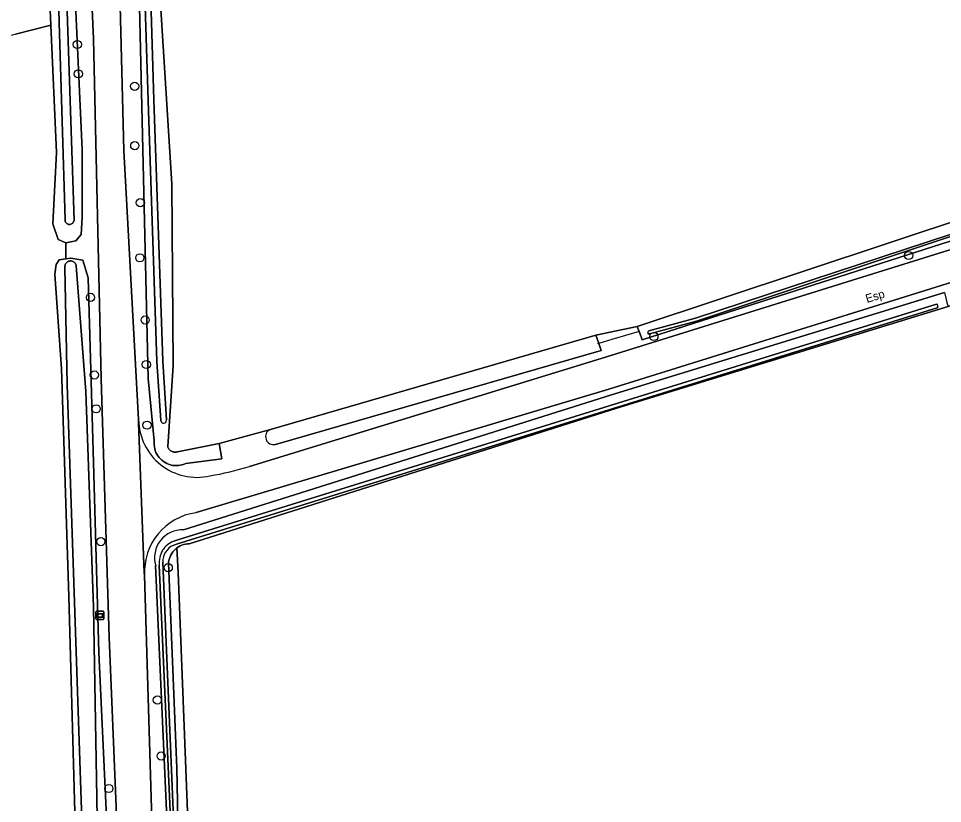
# Model space of a CAD drawing. Extents: x 161385 to 162589, y 388479 to 389756.
# Drawn here: x 161804.9 to 161915.1, y 389332.8 to 389426.5 of the extents above; entities that cross this region are included whole.
import ezdxf

# ---------------------------------------------------------------- set-up
doc = ezdxf.new("R2010")
doc.units = 0
for name, color, linetype in [('IMGEO_Boom', 7, 'Continuous'), ('IMGEO_Bouwland', 7, 'Continuous'), ('IMGEO_Duiker', 7, 'Continuous'), ('IMGEO_Groenvoorziening', 7, 'Continuous'), ('IMGEO_Loofbos', 7, 'Continuous'), ('IMGEO_Oever', 7, 'Continuous'), ('IMGEO_Openbare_ruimte_label', 7, 'Continuous'), ('IMGEO_Rijbaan_lokaal_gesloten', 7, 'Continuous'), ('IMGEO_Verklikker', 7, 'Continuous'), ('IMGEO_Waterloop', 7, 'Continuous')]:
    doc.layers.add(name, color=color, linetype=linetype)

msp = doc.modelspace()

# ---------------------------------------------------------------- linework, layer by layer
at = {"layer": 'IMGEO_Boom'}
for centre in [(161811.95, 389423.37), (161812.07, 389419.87), (161818.79, 389418.39), (161818.81, 389411.3), (161819.47, 389404.5), (161819.41, 389397.92), (161911.08, 389398.2), (161813.53, 389393.2), (161820.05, 389390.51), (161880.71, 389388.54), (161820.19, 389385.2), (161814, 389383.96), (161814.21, 389379.91), (161820.28, 389377.96), (161814.76, 389364.08), (161822.8, 389360.97), (161821.51, 389345.19), (161821.96, 389338.51), (161815.72, 389334.63)]:
    msp.add_circle(centre, 0.489, dxfattribs=at)
at = {"layer": 'IMGEO_Bouwland'}
for points in [[(161820.45, 389451.02), (161823.24, 389406.73), (161823.39, 389385.03), (161822.74, 389375.42), (161822.76, 389375.35), (161822.8, 389375.27), (161822.83, 389375.2), (161822.88, 389375.13), (161822.93, 389375.06), (161822.99, 389375), (161823.05, 389374.95), (161823.12, 389374.9), (161823.19, 389374.86), (161823.26, 389374.82), (161823.34, 389374.79), (161823.42, 389374.77), (161823.5, 389374.76), (161823.58, 389374.75), (161823.67, 389374.75), (161823.75, 389374.76), (161823.83, 389374.77), (161823.91, 389374.79), (161828.86, 389375.76), (161834.99, 389377.46), (161873.79, 389388.71), (161878.71, 389389.73), (161989.22, 389426.42)], [(161924.24, 389389.68), (161923.3, 389394.84), (161915.78, 389392.1), (161876.28, 389380.01), (161825.31, 389363.82), (161825.09, 389363.81), (161824.86, 389363.77), (161824.64, 389363.72), (161824.43, 389363.65), (161824.22, 389363.56), (161824.03, 389363.45), (161823.84, 389363.32), (161824, 389360.41), (161827.33, 389274.85), (161859.89, 389276.6), (161886.85, 389279.08), (161944.1, 389287.48)]]:
    msp.add_lwpolyline(points, dxfattribs=at)
at = {"layer": 'IMGEO_Duiker'}
msp.add_lwpolyline([(161878.94, 389389.15), (161875.71, 389388.18), (161874.14, 389387.71), (161874, 389387.67)], dxfattribs=at)
at = {"layer": 'IMGEO_Groenvoorziening'}
for points in [[(161803.61, 389506.63), (161806.15, 389500), (161807.11, 389497.5), (161809.67, 389488.19), (161813.64, 389468.06), (161815.8, 389449.75), (161816.99, 389431.15), (161817.52, 389410.72), (161819.27, 389378.64)], [(161822.47, 389183.9), (161819.9, 389250), (161818.24, 389292.85), (161817.88, 389301.55), (161815.76, 389352.66), (161814.81, 389383.51), (161813.89, 389424.04), (161813.4, 389434.81), (161812.54, 389448.61), (161810.15, 389467.29), (161806.16, 389487.18), (161804.33, 389495.22)], [(162015.57, 389425.19), (162052.22, 389436.6), (162077.56, 389444.49), (162110.6, 389453.36), (162116.48, 389455.97), (162132.77, 389460.73), (162149.28, 389466.12), (162149.51, 389465.17), (162151.86, 389465.92), (162152.81, 389469.35), (162149.94, 389468.39), (162101.79, 389453.37), (162051.71, 389438.12), (162010.92, 389425.7), (162000, 389422.15), (161923.01, 389397.14), (161875.33, 389382.27), (161826.12, 389367.53)], [(161834.99, 389377.46), (161828.86, 389375.76), (161829.18, 389373.96), (161824.91, 389373.4), (161824.69, 389373.31), (161824.47, 389373.23), (161824.24, 389373.18), (161824.01, 389373.15), (161823.77, 389373.14), (161823.54, 389373.15), (161823.3, 389373.17), (161823.07, 389373.23), (161822.85, 389373.3), (161822.63, 389373.39), (161822.42, 389373.5), (161822.22, 389373.63), (161822.04, 389373.77), (161821.87, 389373.93), (161821.71, 389374.11), (161821.57, 389374.3), (161821.45, 389374.5), (161821.34, 389374.71), (161821.26, 389374.93), (161821.19, 389375.16), (161821.15, 389375.39), (161821.13, 389375.62), (161821.12, 389375.86), (161821.14, 389376.09), (161820.42, 389383.54), (161819.1, 389439.9)], [(161811.61, 389430.85), (161812.54, 389410.84), (161812.53, 389402.73), (161812.43, 389400.71), (161811.8, 389399.94), (161810.6, 389399.73), (161810.58, 389397.81), (161811.2, 389397.88), (161812.6, 389397.63), (161813.27, 389395.52), (161813.9, 389373.52), (161814.54, 389350.83), (161815.58, 389327.78), (161816.24, 389306.78), (161816.21, 389297.23), (161817.06, 389274.16), (161818.28, 389246.31), (161819.3, 389221.36)], [(161993.88, 389428.52), (161989.22, 389426.42), (161989.4, 389425.6), (161989.65, 389424.43), (161918.01, 389400.54), (161879.32, 389388.15), (161879.02, 389388.93), (161878.94, 389389.15), (161878.71, 389389.73), (161873.79, 389388.71), (161874.11, 389387.82), (161874.14, 389387.71), (161874.44, 389386.89), (161835.6, 389375.67)], [(161832.48, 389373.05), (161874.41, 389385.9), (161919.07, 389399.82), (162000, 389426.14)], [(161824.61, 389365.48), (161875.64, 389381.59), (161915.36, 389393.78), (161915.57, 389392.95), (161915.65, 389392.6), (161915.78, 389392.1), (161923.3, 389394.84), (161923.24, 389395.11), (161923.11, 389395.64), (161922.91, 389396.45), (161969.32, 389410.88), (161970.06, 389411.11), (162000, 389420.42), (162010.32, 389423.62), (162010.66, 389422.78), (162011.08, 389421.76), (162000, 389418.36), (161974.9, 389410.66), (161975.16, 389409.79), (161974.45, 389409.6), (161974.71, 389408.55), (161987.23, 389412.43), (162020.79, 389422.67)], [(161823.95, 389301.85), (161821.3, 389361.22)], [(161819.99, 389360.06), (161821.73, 389301.74), (161823.28, 389250), (161825.77, 389184.1)]]:
    msp.add_lwpolyline(points, dxfattribs=at)
msp.add_lwpolyline([(161824, 389360.41), (161823.84, 389363.32), (161823.66, 389363.18), (161823.5, 389363.02), (161823.36, 389362.85), (161823.23, 389362.66), (161823.11, 389362.47), (161823.02, 389362.26), (161822.94, 389362.05), (161822.88, 389361.83), (161822.84, 389361.61), (161822.83, 389361.54), (161823.81, 389337.04), (161824.18, 389318.85), (161825.98, 389274.78), (161827.33, 389274.85)], close=True, dxfattribs=at)
for centre, radius, start, end in [((161826.23, 389378.7), 6.96, 180.5146, 282.7849), ((161835.36, 389376.59), 0.95, 113.342, 284.6185), ((161821.17, 389409.71), 38.37, 279.9026, 287.1432), ((161827.07, 389360.49), 7.1, 97.711, 183.4599), ((161824.48, 389362.17), 3.31, 87.6408, 196.6651)]:
    msp.add_arc(centre, radius, start, end, dxfattribs=at)
at = {"layer": 'IMGEO_Loofbos'}
msp.add_lwpolyline([(161808.81, 389425.67), (161808.7, 389428.38), (161808.59, 389430.65), (161808.68, 389431.62), (161809.55, 389432.13), (161810.03, 389432.1), (161809.88, 389436.24), (161808.82, 389435.47), (161807.74, 389435.14), (161807.42, 389436.2), (161802.27, 389434.35), (161794.13, 389432.6), (161776.69, 389428.35), (161757.68, 389423.46), (161743.62, 389419.4), (161742.64, 389408.7), (161760.31, 389413.8), (161779.12, 389418.64), (161796.38, 389422.84), (161804.59, 389424.61)], close=True, dxfattribs=at)
msp.add_lwpolyline([(161731.43, 389292.15), (161809.61, 389302.69), (161812.61, 389303.11), (161812.24, 389309.63), (161811.62, 389333.26), (161810.96, 389357.54), (161810.08, 389384.67), (161809.29, 389395.96), (161809.45, 389397.13), (161809.81, 389397.68), (161810.58, 389397.81), (161810.6, 389399.73), (161809.68, 389400.12), (161809.05, 389401.99), (161809.48, 389410.49), (161808.81, 389425.67), (161804.59, 389424.61)], dxfattribs=at)
at = {"layer": 'IMGEO_Oever'}
for points in [[(161821.96, 389378.42), (161821.91, 389378.53), (161821.46, 389385.56), (161820.41, 389416.69), (161819.7, 389439.19), (161818.14, 389460.28), (161816.84, 389468.86), (161812.8, 389487.76), (161811.27, 389494.42), (161808.33, 389503.15)], [(161808.86, 389503.38), (161811.95, 389494.51), (161813.47, 389487.84), (161817.52, 389468.95), (161818.82, 389460.36), (161820.39, 389439.29), (161821.08, 389416.78)], [(161819.1, 389439.9), (161820.42, 389383.54), (161821.14, 389376.09), (161821.12, 389375.86), (161821.13, 389375.62), (161821.15, 389375.39), (161821.19, 389375.16), (161821.26, 389374.93), (161821.34, 389374.71), (161821.45, 389374.5), (161821.57, 389374.3), (161821.71, 389374.11), (161821.87, 389373.93), (161822.04, 389373.77), (161822.22, 389373.63), (161822.42, 389373.5), (161822.63, 389373.39), (161822.85, 389373.3), (161823.07, 389373.23), (161823.3, 389373.17), (161823.54, 389373.15), (161823.77, 389373.14), (161824.01, 389373.15), (161824.24, 389373.18), (161824.47, 389373.23), (161824.69, 389373.31), (161824.91, 389373.4), (161829.18, 389373.96), (161828.86, 389375.76), (161823.91, 389374.79), (161823.83, 389374.77), (161823.75, 389374.76), (161823.67, 389374.75), (161823.58, 389374.75), (161823.5, 389374.76), (161823.42, 389374.77), (161823.34, 389374.79), (161823.26, 389374.82), (161823.19, 389374.86), (161823.12, 389374.9), (161823.05, 389374.95), (161822.99, 389375), (161822.93, 389375.06), (161822.88, 389375.13), (161822.83, 389375.2), (161822.8, 389375.27), (161822.76, 389375.35), (161822.74, 389375.42), (161823.39, 389385.03), (161823.24, 389406.73), (161820.45, 389451.02)], [(161810.64, 389430.92), (161811.59, 389402.4), (161811.44, 389402.06), (161811.1, 389401.89), (161811.05, 389401.89), (161811, 389401.89), (161810.96, 389401.89), (161810.91, 389401.9), (161810.86, 389401.92), (161810.82, 389401.94), (161810.77, 389401.96), (161810.73, 389401.99), (161810.7, 389402.02), (161810.66, 389402.05), (161810.63, 389402.09), (161810.6, 389402.12), (161810.57, 389402.17), (161810.55, 389402.21), (161810.53, 389402.26), (161810.52, 389402.3), (161810.51, 389402.35), (161810.51, 389402.4), (161810.51, 389402.45), (161809.8, 389425.98), (161809.66, 389430.77)], [(161988.29, 389424.39), (161988.29, 389424.35), (161988.22, 389424.27), (161988.2, 389424.25), (161988.09, 389424.21), (161970.95, 389418.43), (161944.43, 389409.78), (161916.2, 389400.52), (161885.78, 389390.38), (161880.2, 389388.85), (161880.04, 389388.86), (161880.01, 389388.88), (161880, 389388.9)], [(161879.99, 389389.11), (161880.11, 389389.21), (161885.68, 389390.74), (161916.14, 389400.74), (161930.23, 389405.46), (161944.37, 389410), (161970.89, 389418.71)], [(161821.08, 389416.78), (161822.14, 389385.64), (161822.58, 389378.61)], [(161819.3, 389221.36), (161818.28, 389246.31), (161817.06, 389274.16), (161816.21, 389297.23), (161816.24, 389306.78), (161815.58, 389327.78), (161814.54, 389350.83), (161813.9, 389373.52), (161813.27, 389395.52), (161812.6, 389397.63), (161811.2, 389397.88), (161810.58, 389397.81), (161809.81, 389397.68), (161809.45, 389397.13), (161809.29, 389395.96), (161810.08, 389384.67), (161810.96, 389357.54), (161811.62, 389333.26), (161812.24, 389309.63), (161812.61, 389303.11), (161813.67, 389283.96), (161814.96, 389258.6), (161815.63, 389234.8)], [(161813.36, 389304.94), (161810.76, 389382.77), (161810.48, 389396.81), (161810.48, 389396.84), (161810.48, 389396.9), (161810.49, 389396.96), (161810.5, 389397.02), (161810.51, 389397.08), (161810.53, 389397.14), (161810.56, 389397.19), (161810.59, 389397.24), (161810.62, 389397.29), (161810.66, 389397.34), (161810.71, 389397.38), (161810.75, 389397.42), (161810.8, 389397.45), (161810.86, 389397.48), (161810.91, 389397.51), (161810.97, 389397.53), (161811.03, 389397.54), (161811.09, 389397.55), (161811.12, 389397.55), (161811.18, 389397.55), (161811.24, 389397.55), (161811.3, 389397.54), (161811.36, 389397.52), (161811.41, 389397.5), (161811.47, 389397.48), (161811.52, 389397.45), (161811.57, 389397.41), (161811.62, 389397.37), (161811.66, 389397.33), (161811.7, 389397.28), (161811.73, 389397.23), (161811.76, 389397.18), (161811.79, 389397.12), (161811.81, 389397.07), (161811.82, 389397.01), (161811.83, 389396.95), (161812.98, 389381.98), (161813.88, 389356.25), (161814.79, 389303.88)], [(161915.36, 389393.78), (161875.64, 389381.59), (161824.61, 389365.48)], [(161823.48, 389364.12), (161824.05, 389364.32), (161914.39, 389392.4), (161914.51, 389392.35)], [(161823.81, 389337.04), (161822.83, 389361.54), (161822.84, 389361.61), (161822.88, 389361.83), (161822.94, 389362.05), (161823.02, 389362.26), (161823.11, 389362.47), (161823.23, 389362.66), (161823.36, 389362.85), (161823.5, 389363.02), (161823.66, 389363.18), (161823.84, 389363.32), (161824.03, 389363.45), (161824.22, 389363.56), (161824.43, 389363.65), (161824.64, 389363.72), (161824.86, 389363.77), (161825.09, 389363.81), (161825.31, 389363.82), (161876.28, 389380.01), (161915.78, 389392.1)], [(161914.58, 389392.07), (161914.48, 389391.97), (161823.79, 389363.78)], [(161823.79, 389363.78), (161823.4, 389363.63)], [(161822.16, 389361.63), (161823.99, 389317.71), (161825.71, 389274.91), (161825.67, 389274.77), (161825.63, 389274.73), (161825.56, 389274.72), (161825.49, 389274.74), (161825.46, 389274.77), (161825.4, 389274.91), (161823.85, 389313.22), (161821.71, 389361.27)], [(161821.3, 389361.22), (161823.95, 389301.85), (161825.17, 389274.39), (161825.33, 389273.84), (161825.52, 389273.7), (161825.69, 389273.77), (161825.73, 389273.79), (161825.99, 389274.56), (161825.98, 389274.78), (161824.18, 389318.85), (161823.81, 389337.04)]]:
    msp.add_lwpolyline(points, dxfattribs=at)
for points in [[(161811.61, 389430.85), (161811.04, 389432.11), (161810.03, 389432.1), (161809.55, 389432.13), (161808.68, 389431.62), (161808.59, 389430.65), (161808.7, 389428.38), (161808.81, 389425.67), (161809.48, 389410.49), (161809.05, 389401.99), (161809.68, 389400.12), (161810.6, 389399.73), (161811.8, 389399.94), (161812.43, 389400.71), (161812.53, 389402.73), (161812.54, 389410.84)], [(161989.65, 389424.43), (161989.4, 389425.6), (161989.22, 389426.42), (161878.71, 389389.73), (161878.94, 389389.15), (161879.02, 389388.93), (161879.32, 389388.15), (161918.01, 389400.54)]]:
    msp.add_lwpolyline(points, close=True, dxfattribs=at)
for centre, radius, start, end in [((161914.36, 389392.16), 0.234, 336.7846, 51.386), ((161880.3, 389389.01), 0.325, 161.7242, 200.4075), ((161822.29, 389378.56), 0.366, 203.164, 267.6681), ((161822.27, 389378.51), 0.314, 270.6274, 319.7514), ((161822.03, 389378.58), 0.551, 330.9939, 3.6273), ((161824.48, 389362.17), 3.31, 87.6408, 196.6651), ((161824.48, 389361.45), 2.85, 110.6205, 146.8708), ((161825.37, 389361.37), 3.66, 153.4094, 181.491), ((161824.26, 389361.71), 2.1, 114.1249, 182.1801)]:
    msp.add_arc(centre, radius, start, end, dxfattribs=at)
at = {"layer": 'IMGEO_Rijbaan_lokaal_gesloten'}
for points in [[(162274.51, 389513.54), (162284.77, 389517.62), (162283.07, 389521.76), (162282.4, 389521.48), (162273.98, 389518.09), (162256.73, 389511.13), (162234.04, 389502.53), (162227.24, 389500), (162209.08, 389493.03), (162180.59, 389482.67), (162149.26, 389472.47), (162113.07, 389461.06), (162103.55, 389458.09), (162050.46, 389441.86), (162014.71, 389430.93), (162014.07, 389430.72), (162008.66, 389428.95), (162007.84, 389428.69), (162000, 389426.14), (161919.07, 389399.82), (161874.41, 389385.9), (161832.48, 389373.05)], [(161826.12, 389367.53), (161875.33, 389382.27), (161923.01, 389397.14), (162000, 389422.15), (162010.92, 389425.7), (162051.71, 389438.12), (162101.79, 389453.37), (162149.94, 389468.39), (162152.81, 389469.35), (162156.6, 389470.63), (162181.39, 389478.96), (162191.34, 389482.09), (162232.31, 389497.1), (162253.52, 389505.21), (162274.51, 389513.54)], [(161825.77, 389184.1), (161823.28, 389250), (161821.73, 389301.74), (161819.99, 389360.06), (161819.95, 389360.35), (161819.25, 389378.23), (161819.27, 389378.64), (161817.52, 389410.72), (161816.99, 389431.15), (161815.8, 389449.75), (161813.64, 389468.06), (161809.67, 389488.19), (161807.11, 389497.5), (161806.15, 389500), (161803.61, 389506.63)], [(161804.33, 389495.22), (161806.16, 389487.18), (161810.15, 389467.29), (161812.54, 389448.61), (161813.4, 389434.81), (161813.89, 389424.04), (161814.81, 389383.51), (161815.76, 389352.66), (161817.88, 389301.55), (161818.24, 389292.85), (161819.9, 389250), (161822.47, 389183.9)], [(161819.27, 389378.64), (161819.25, 389378.23), (161819.95, 389360.35), (161819.99, 389360.06)]]:
    msp.add_lwpolyline(points, dxfattribs=at)
for centre, radius, start, end in [((161826.23, 389378.7), 6.96, 180.5146, 282.7849), ((161821.17, 389409.71), 38.37, 279.9026, 287.1432), ((161827.07, 389360.49), 7.1, 97.711, 183.4599)]:
    msp.add_arc(centre, radius, start, end, dxfattribs=at)
at = {"layer": 'IMGEO_Verklikker'}
for p, q in [((161814.16, 389354.88), (161814.16, 389355.68)), ((161814.16, 389355.68), (161814.16, 389354.88)), ((161814.26, 389355.78), (161815.04, 389355.78)), ((161815.04, 389355.78), (161814.26, 389355.78)), ((161815.14, 389355.68), (161815.14, 389354.88)), ((161815.14, 389354.88), (161815.14, 389355.68)), ((161815.04, 389354.78), (161814.26, 389354.78)), ((161814.26, 389354.78), (161815.04, 389354.78))]:
    msp.add_line(p, q, dxfattribs=at)
for points in [[(161814.26, 389355.51), (161815.04, 389355.51), (161815.04, 389355.04), (161814.26, 389355.04), (161814.26, 389355.51)], [(161814.32, 389355.44), (161814.32, 389355.11), (161814.98, 389355.11), (161814.98, 389355.44), (161814.32, 389355.44)]]:
    msp.add_lwpolyline(points, dxfattribs=at)
for centre, start, end in [((161814.26, 389355.68), 90, 180), ((161814.26, 389355.68), 90, 180), ((161815.04, 389355.68), 0, 90), ((161815.04, 389355.68), 360, 90), ((161814.26, 389354.88), 180, 270), ((161814.26, 389354.88), 180, 270), ((161815.04, 389354.88), 270, 0), ((161815.04, 389354.88), 270, 0)]:
    msp.add_arc(centre, 0.1, start, end, dxfattribs=at)
at = {"layer": 'IMGEO_Waterloop'}
for points in [[(161808.33, 389503.15), (161811.27, 389494.42), (161812.8, 389487.76), (161816.84, 389468.86), (161818.14, 389460.28), (161819.7, 389439.19), (161820.41, 389416.69), (161821.46, 389385.56), (161821.91, 389378.53), (161821.96, 389378.42)], [(161822.58, 389378.61), (161822.14, 389385.64), (161821.08, 389416.78), (161820.39, 389439.29), (161818.82, 389460.36), (161817.52, 389468.95), (161813.47, 389487.84), (161811.95, 389494.51), (161808.86, 389503.38)], [(161809.66, 389430.77), (161809.8, 389425.98), (161810.51, 389402.45), (161810.51, 389402.4), (161810.51, 389402.35), (161810.52, 389402.3), (161810.53, 389402.26), (161810.55, 389402.21), (161810.57, 389402.17), (161810.6, 389402.12), (161810.63, 389402.09), (161810.66, 389402.05), (161810.7, 389402.02), (161810.73, 389401.99), (161810.77, 389401.96), (161810.82, 389401.94), (161810.86, 389401.92), (161810.91, 389401.9), (161810.96, 389401.89), (161811, 389401.89), (161811.05, 389401.89), (161811.1, 389401.89), (161811.44, 389402.06), (161811.59, 389402.4), (161810.64, 389430.92)], [(161987.97, 389424.63), (161970.89, 389418.71), (161944.37, 389410), (161930.23, 389405.46), (161916.14, 389400.74), (161885.68, 389390.74), (161880.11, 389389.21), (161879.99, 389389.11)], [(161880, 389388.9), (161880.01, 389388.88), (161880.04, 389388.86), (161880.2, 389388.85), (161885.78, 389390.38), (161916.2, 389400.52), (161944.43, 389409.78), (161970.95, 389418.43)], [(161814.79, 389303.88), (161813.88, 389356.25), (161812.98, 389381.98), (161811.83, 389396.95), (161811.82, 389397.01), (161811.81, 389397.07), (161811.79, 389397.12), (161811.76, 389397.18), (161811.73, 389397.23), (161811.7, 389397.28), (161811.66, 389397.33), (161811.62, 389397.37), (161811.57, 389397.41), (161811.52, 389397.45), (161811.47, 389397.48), (161811.41, 389397.5), (161811.36, 389397.52), (161811.3, 389397.54), (161811.24, 389397.55), (161811.18, 389397.55), (161811.12, 389397.55), (161811.09, 389397.55), (161811.03, 389397.54), (161810.97, 389397.53), (161810.91, 389397.51), (161810.86, 389397.48), (161810.8, 389397.45), (161810.75, 389397.42), (161810.71, 389397.38), (161810.66, 389397.34), (161810.62, 389397.29), (161810.59, 389397.24), (161810.56, 389397.19), (161810.53, 389397.14), (161810.51, 389397.08), (161810.5, 389397.02), (161810.49, 389396.96), (161810.48, 389396.9), (161810.48, 389396.84), (161810.48, 389396.81), (161810.76, 389382.77), (161813.36, 389304.94)], [(161914.51, 389392.35), (161914.39, 389392.4), (161824.05, 389364.32), (161823.48, 389364.12)], [(161823.4, 389363.63), (161823.79, 389363.78), (161914.48, 389391.97), (161914.58, 389392.07)], [(161874.44, 389386.89), (161874.14, 389387.71), (161874.11, 389387.82), (161873.79, 389388.71), (161834.99, 389377.46)], [(161835.6, 389375.67), (161874.44, 389386.89)], [(161821.71, 389361.27), (161823.85, 389313.22), (161825.4, 389274.91), (161825.46, 389274.77), (161825.49, 389274.74), (161825.56, 389274.72), (161825.63, 389274.73), (161825.67, 389274.77), (161825.71, 389274.91), (161823.99, 389317.71), (161822.16, 389361.63)]]:
    msp.add_lwpolyline(points, dxfattribs=at)
for centre, radius, start, end in [((161914.36, 389392.16), 0.234, 336.7846, 51.386), ((161880.3, 389389.01), 0.325, 161.7242, 200.4075), ((161822.29, 389378.56), 0.366, 203.164, 267.6681), ((161822.27, 389378.51), 0.314, 270.6274, 319.7514), ((161822.03, 389378.58), 0.551, 330.9939, 3.6273), ((161835.36, 389376.59), 0.95, 113.342, 284.6185), ((161824.48, 389361.45), 2.85, 110.6205, 146.8708), ((161825.37, 389361.37), 3.66, 153.4094, 181.491), ((161824.26, 389361.71), 2.1, 114.1249, 182.1801)]:
    msp.add_arc(centre, radius, start, end, dxfattribs=at)

# ---------------------------------------------------------------- texts
at = {"layer": 'IMGEO_Openbare_ruimte_label'}
msp.add_text('Esp', height=1, rotation=16.8584, dxfattribs=at).set_placement((161906.12, 389392.54))

doc.saveas('drawing.dxf')
